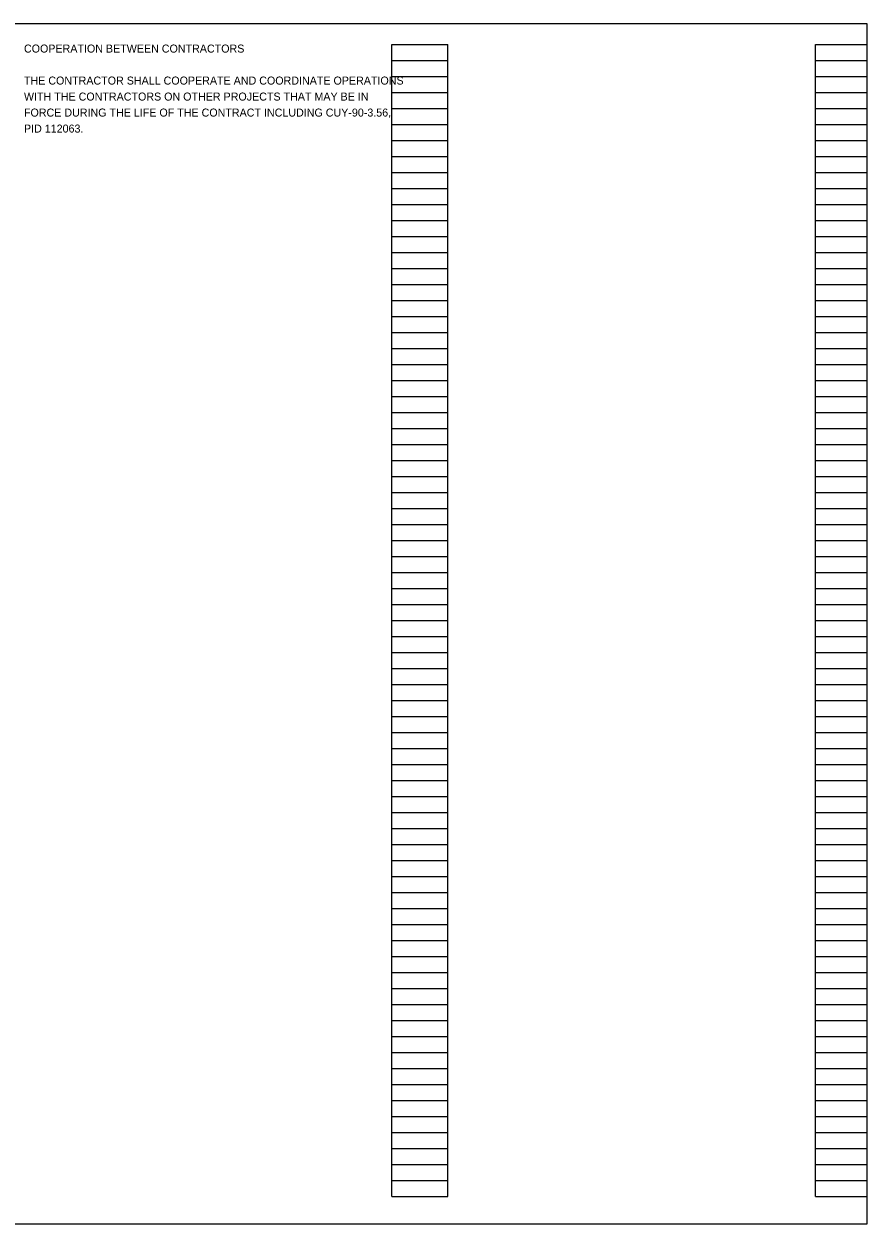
# Model space of a CAD drawing. Extents: x 0 to 2132911, y 0 to 658646.
# Drawn here: x 51.24 to 66, y 0.5 to 21.5 of the extents above; entities that cross this region are included whole.
import ezdxf

# ---------------------------------------------------------------- set-up
doc = ezdxf.new("R2010")
doc.units = 0
for name, color, linetype in [('SC_Scratch1', 7, 'Continuous'), ('SH_Data', 7, 'Continuous'), ('SH_Text', 7, 'Continuous')]:
    doc.layers.add(name, color=color, linetype=linetype)

msp = doc.modelspace()

# ---------------------------------------------------------------- linework, layer by layer
at = {"layer": 'SC_Scratch1'}
msp.add_lwpolyline([(35.5, 0.5), (66, 0.5), (66, 21.5), (35.5, 21.5)], close=True, dxfattribs=at)
at = {"layer": 'SH_Data'}
for p, q in [((57.68, 0.98), (57.68, 21.14)), ((57.68, 21.14), (58.66, 21.14)), ((58.66, 0.98), (58.66, 21.14)), ((65.1, 0.98), (65.1, 21.14)), ((65.1, 21.14), (66, 21.14)), ((66, 0.98), (66, 21.14)), ((57.68, 20.86), (58.66, 20.86)), ((65.1, 20.86), (66, 20.86)), ((57.68, 20.58), (58.66, 20.58)), ((65.1, 20.58), (66, 20.58)), ((57.68, 20.3), (58.66, 20.3)), ((65.1, 20.3), (66, 20.3)), ((57.68, 20.02), (58.66, 20.02)), ((65.1, 20.02), (66, 20.02)), ((57.68, 19.74), (58.66, 19.74)), ((65.1, 19.74), (66, 19.74)), ((57.68, 19.46), (58.66, 19.46)), ((65.1, 19.46), (66, 19.46)), ((57.68, 19.18), (58.66, 19.18)), ((65.1, 19.18), (66, 19.18)), ((57.68, 18.9), (58.66, 18.9)), ((65.1, 18.9), (66, 18.9)), ((57.68, 18.62), (58.66, 18.62)), ((65.1, 18.62), (66, 18.62)), ((57.68, 18.34), (58.66, 18.34)), ((65.1, 18.34), (66, 18.34)), ((57.68, 18.06), (58.66, 18.06)), ((65.1, 18.06), (66, 18.06)), ((57.68, 17.78), (58.66, 17.78)), ((65.1, 17.78), (66, 17.78)), ((57.68, 17.5), (58.66, 17.5)), ((65.1, 17.5), (66, 17.5)), ((57.68, 17.22), (58.66, 17.22)), ((65.1, 17.22), (66, 17.22)), ((57.68, 16.94), (58.66, 16.94)), ((65.1, 16.94), (66, 16.94)), ((57.68, 16.66), (58.66, 16.66)), ((65.1, 16.66), (66, 16.66)), ((57.68, 16.38), (58.66, 16.38)), ((65.1, 16.38), (66, 16.38)), ((57.68, 16.1), (58.66, 16.1)), ((65.1, 16.1), (66, 16.1)), ((57.68, 15.82), (58.66, 15.82)), ((65.1, 15.82), (66, 15.82)), ((57.68, 15.54), (58.66, 15.54)), ((65.1, 15.54), (66, 15.54)), ((57.68, 15.26), (58.66, 15.26)), ((65.1, 15.26), (66, 15.26)), ((57.68, 14.98), (58.66, 14.98)), ((65.1, 14.98), (66, 14.98)), ((57.68, 14.7), (58.66, 14.7)), ((65.1, 14.7), (66, 14.7)), ((57.68, 14.42), (58.66, 14.42)), ((65.1, 14.42), (66, 14.42)), ((57.68, 14.14), (58.66, 14.14)), ((65.1, 14.14), (66, 14.14)), ((57.68, 13.86), (58.66, 13.86)), ((65.1, 13.86), (66, 13.86)), ((57.68, 13.58), (58.66, 13.58)), ((65.1, 13.58), (66, 13.58)), ((57.68, 13.3), (58.66, 13.3)), ((65.1, 13.3), (66, 13.3)), ((57.68, 13.02), (58.66, 13.02)), ((65.1, 13.02), (66, 13.02)), ((57.68, 12.74), (58.66, 12.74)), ((65.1, 12.74), (66, 12.74)), ((57.68, 12.46), (58.66, 12.46)), ((65.1, 12.46), (66, 12.46)), ((57.68, 12.18), (58.66, 12.18)), ((65.1, 12.18), (66, 12.18)), ((57.68, 11.9), (58.66, 11.9)), ((65.1, 11.9), (66, 11.9)), ((57.68, 11.62), (58.66, 11.62)), ((65.1, 11.62), (66, 11.62)), ((57.68, 11.34), (58.66, 11.34)), ((65.1, 11.34), (66, 11.34)), ((57.68, 11.06), (58.66, 11.06)), ((65.1, 11.06), (66, 11.06)), ((57.68, 10.78), (58.66, 10.78)), ((65.1, 10.78), (66, 10.78)), ((57.68, 10.5), (58.66, 10.5)), ((65.1, 10.5), (66, 10.5)), ((57.68, 10.22), (58.66, 10.22)), ((65.1, 10.22), (66, 10.22)), ((57.68, 9.94), (58.66, 9.94)), ((65.1, 9.94), (66, 9.94)), ((57.68, 9.66), (58.66, 9.66)), ((65.1, 9.66), (66, 9.66)), ((57.68, 9.38), (58.66, 9.38)), ((65.1, 9.38), (66, 9.38)), ((57.68, 9.1), (58.66, 9.1)), ((65.1, 9.1), (66, 9.1)), ((57.68, 8.82), (58.66, 8.82)), ((65.1, 8.82), (66, 8.82)), ((57.68, 8.54), (58.66, 8.54)), ((65.1, 8.54), (66, 8.54)), ((57.68, 8.26), (58.66, 8.26)), ((65.1, 8.26), (66, 8.26)), ((57.68, 7.98), (58.66, 7.98)), ((65.1, 7.98), (66, 7.98)), ((57.68, 7.7), (58.66, 7.7)), ((65.1, 7.7), (66, 7.7)), ((57.68, 7.42), (58.66, 7.42)), ((65.1, 7.42), (66, 7.42)), ((57.68, 7.14), (58.66, 7.14)), ((65.1, 7.14), (66, 7.14)), ((57.68, 6.86), (58.66, 6.86)), ((65.1, 6.86), (66, 6.86)), ((57.68, 6.58), (58.66, 6.58)), ((65.1, 6.58), (66, 6.58)), ((57.68, 6.3), (58.66, 6.3)), ((65.1, 6.3), (66, 6.3)), ((57.68, 6.02), (58.66, 6.02)), ((65.1, 6.02), (66, 6.02)), ((57.68, 5.74), (58.66, 5.74)), ((65.1, 5.74), (66, 5.74)), ((57.68, 5.46), (58.66, 5.46)), ((65.1, 5.46), (66, 5.46)), ((57.68, 5.18), (58.66, 5.18)), ((65.1, 5.18), (66, 5.18)), ((57.68, 4.9), (58.66, 4.9)), ((65.1, 4.9), (66, 4.9)), ((57.68, 4.62), (58.66, 4.62)), ((65.1, 4.62), (66, 4.62)), ((57.68, 4.34), (58.66, 4.34)), ((65.1, 4.34), (66, 4.34)), ((57.68, 4.06), (58.66, 4.06)), ((65.1, 4.06), (66, 4.06)), ((57.68, 3.78), (58.66, 3.78)), ((65.1, 3.78), (66, 3.78)), ((57.68, 3.5), (58.66, 3.5)), ((65.1, 3.5), (66, 3.5)), ((57.68, 3.22), (58.66, 3.22)), ((65.1, 3.22), (66, 3.22)), ((57.68, 2.94), (58.66, 2.94)), ((65.1, 2.94), (66, 2.94)), ((57.68, 2.66), (58.66, 2.66)), ((65.1, 2.66), (66, 2.66)), ((57.68, 2.38), (58.66, 2.38)), ((65.1, 2.38), (66, 2.38)), ((57.68, 2.1), (58.66, 2.1)), ((65.1, 2.1), (66, 2.1)), ((57.68, 1.82), (58.66, 1.82)), ((65.1, 1.82), (66, 1.82)), ((57.68, 1.54), (58.66, 1.54)), ((65.1, 1.54), (66, 1.54)), ((57.68, 1.26), (58.66, 1.26)), ((65.1, 1.26), (66, 1.26)), ((57.68, 0.98), (58.66, 0.98)), ((65.1, 0.98), (66, 0.98))]:
    msp.add_line(p, q, dxfattribs=at)

# ---------------------------------------------------------------- texts
at = {"layer": 'SH_Text'}
for s, p in [('COOPERATION BETWEEN CONTRACTORS', (51.24, 21)), ('THE CONTRACTOR SHALL COOPERATE AND COORDINATE OPERATIONS ', (51.24, 20.44)), ('WITH THE CONTRACTORS ON OTHER PROJECTS THAT MAY BE IN ', (51.24, 20.16)), ('FORCE DURING THE LIFE OF THE CONTRACT INCLUDING CUY-90-3.56, ', (51.24, 19.88)), ('PID 112063.', (51.24, 19.6))]:
    msp.add_text(s, height=0.14, dxfattribs=at).set_placement(p)

doc.saveas('drawing.dxf')
